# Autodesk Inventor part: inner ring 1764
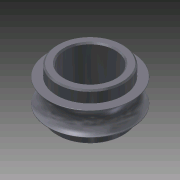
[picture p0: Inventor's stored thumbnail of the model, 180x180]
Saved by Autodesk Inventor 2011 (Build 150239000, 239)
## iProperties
Created: 2009-01
Part Number: inner ring 1764
Document SubType Name: Modeling
Designer: pmulligan
Density: 1 g/cm^3
Author: pmulligan
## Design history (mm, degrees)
sketch "Sketch1"
  geometry: L1 (-25.486, -2.288)-(-25.486, -4.462); L2 (-25.486, -9.034)-(-25.486, -11.209); L3 (-25.486, -11.209)-(-23.899, -11.209); L4 (-23.899, -11.209)-(-23.899, -2.288); L5 (-23.899, -2.288)-(-25.486, -2.288); L6 (-19.136, -1.735)-(-19.136, -11.209); L7 (-27.039, -9.034)-(-25.486, -9.034); L8 (-25.486, -4.462)-(-27.039, -4.462); A1 r 2.286 centre (-27.874, -6.748) between (-27.066, -8.887) and (-27.066, -4.61); A2 r 0.076 centre (-27.039, -4.538) between (-27.039, -4.462) and (-27.066, -4.61); A3 r 0.076 centre (-27.039, -8.958) between (-27.066, -8.887) and (-27.039, -9.034)
  constraints: 16 end point, 6 point on circle, 6 tangent, 3 centre point, 2 collinear, 2 parallel, 2 perpendicular, 1 equal radius, 1 vertical
  dimensions: "d0" = 2.17472 distance of L2.start L2.end; "d2" = 2.17472 distance of L1.start L1.end; "d3" = 1.5875 distance of L2.end L3.end; "d7" = 4.572 diameter of A1; "d8" = 0.0762 radius of A2; "d16" = 4.7625 distance between parallel lines of L6 L4; "d20" = 3.14037 distance from line of L8.end L4; "d21" = 3.9751 distance from line of A1.centre L4
revolve "Revolution1" sketch "Sketch1" stored, may be unused: angle "d9" = 90 deg
chamfer "Chamfer1" distance "d10" = 0.254; stored, may be unused: second distance "d11" = 3.175, angle "d12" = 45 deg
chamfer "Chamfer2" distance "d13" = 0.254; stored, may be unused: second distance "d14" = 3.175, angle "d15" = 45 deg
body "Solid1"
